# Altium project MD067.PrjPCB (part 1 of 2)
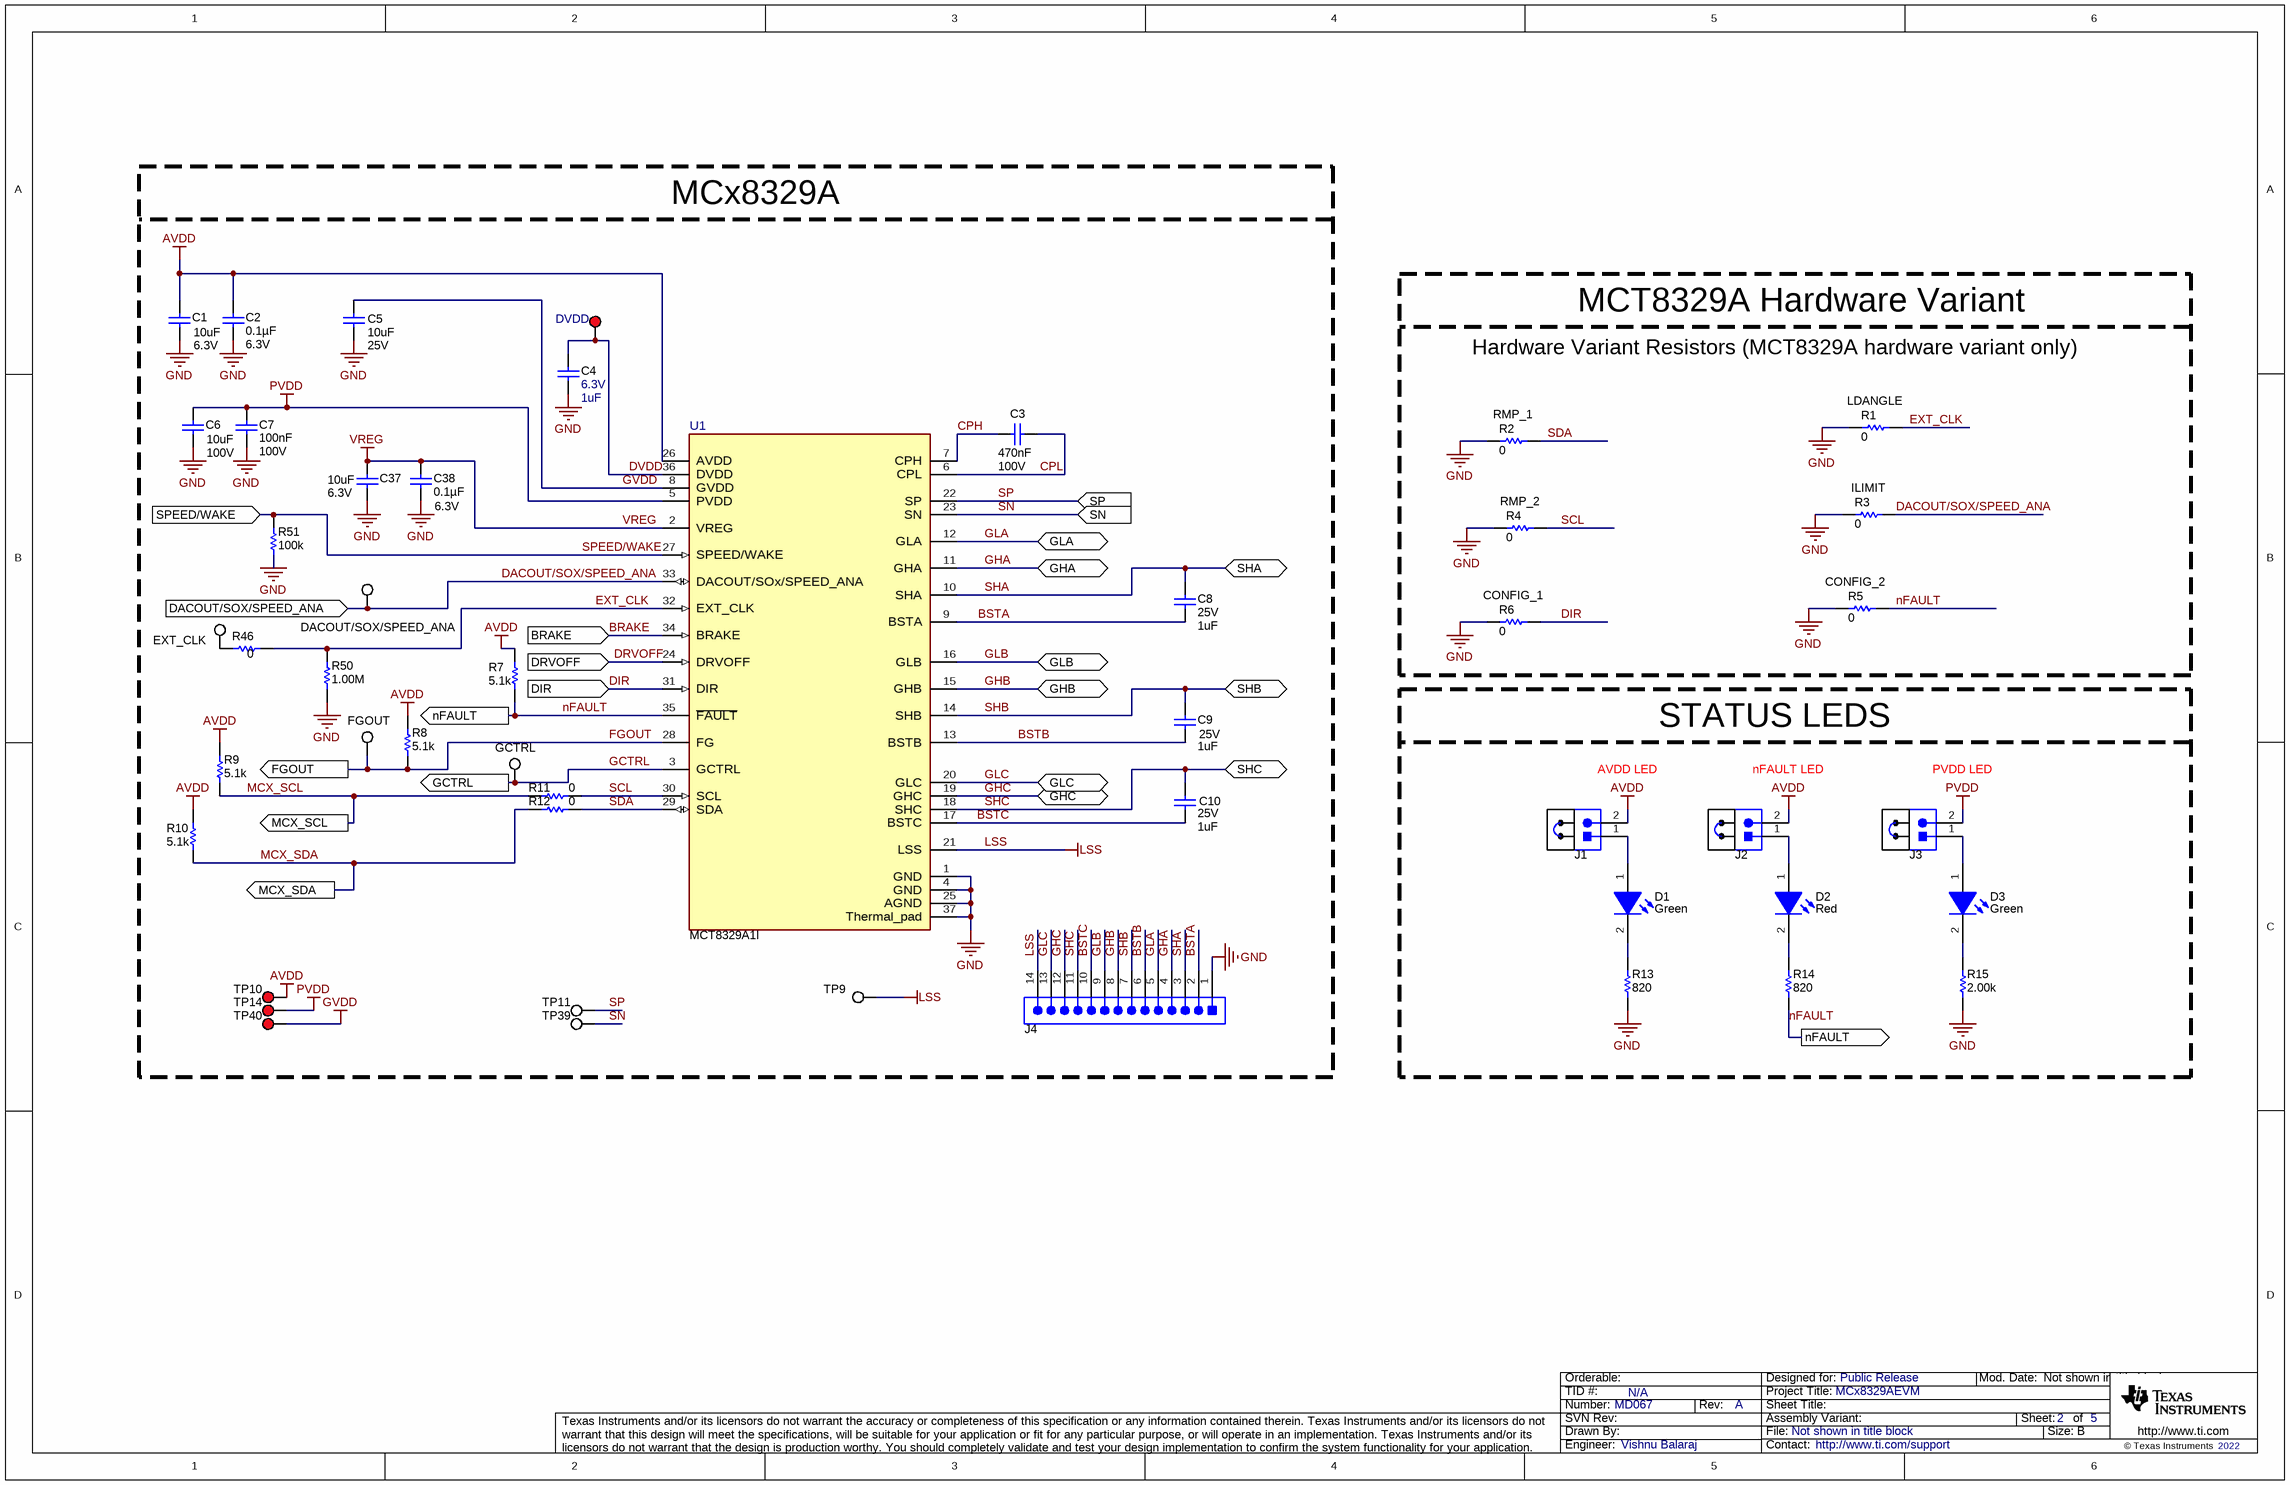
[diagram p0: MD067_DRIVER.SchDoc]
CopyrightYear: 2022; PCB_Layout: Vishnu Balaraj; PCB_Rev: A; PRJ_Customer: Public Release; PRJ_Engineer: Vishnu Balaraj; PRJ_Number: MD067; PRJ_Title: MCx8329AEVM; SCH_Rev: A; TechSupport: http://www.ti.com/support; TID: N/A
5 sheets, 235 parts. Net scope: flat (ports and power ports of the same name join across sheets).
Board file: MD067.PcbDoc
Sheets:
  MD067_DRIVER.SchDoc
  MD067_FETS_AND_POWER_STAGE.SchDoc
  MD067_HARDWARE.SchDoc
  MD067_POWER_AND_CONNECTORS.SchDoc
  MD067_INTERFACE.SchDoc

## Sheet MD067_DRIVER.SchDoc
size 431 x 279 mm; Date: Not shown in title block; ApprovedBy: Not shown in title block; CheckedBy: Not shown in title block; Author: Not shown in title block; CompanyName: Not shown in title block; Engineer: Not shown in title block; Organization: Not shown in title block; Address1: Not shown in title block; Address2: Not shown in title block; Address3: Not shown in title block; Address4: Not shown in title block; DocumentNumber: 2; Revision: Use project parameter SCH_Rev; SheetNumber: 2; SheetTotal: 5; PageSetup: Record=PageOptions¦CenterHorizontal=True¦CenterVertical=True¦PrintScale=1.00¦XCorrection=1.00¦YCorrection=1.00¦PrintKind=0¦BorderSize=5000000¦LeftOffset=0¦BottomOffset=0¦Orientation=2¦PaperLength=1000¦PaperWidth=1000¦Scale=100¦PaperSource=15¦PrintQuality=600¦MediaType=1¦DitherType=10¦PaperKind=Letter¦PrintScaleMode=1

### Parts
C1  VDC_V: 6.3V  ValueDisplayed: 10uF  [0603]  (hidden comment: C0603C106M9PACTU)
C2  ValueDisplayed: 0.1µF  VDC_V: 6.3V  [0603]  (hidden comment: C0603C104K9PAC7867)
C3  Cap_F: 470nF  VDC_V: 100V  [0805_HV]  (hidden comment: GRM21BR72A474KA73L)
C4  VDC_V: 6.3V  ValueDisplayed: 1uF  [0603]  (hidden comment: GRM188R60J105KA01D)
C5  VDC_V: 25V  ValueDisplayed: 10uF  [0603L]  (hidden comment: C1608X5R1E106M080AC)
C6  VDC_V: 100V  ValueDisplayed: 10uF  [2220_280L]  (hidden comment: 22201C106MAT2A)
C7  Cap_F: 100nF  VDC_V: 100V  [0603L]  (hidden comment: GRM188R72A104KA35J)
C8  VDC_V: 25V  ValueDisplayed: 1uF  [0603L]  (hidden comment: C1608X5R1E105K080AC)
C9  VDC_V: 25V  ValueDisplayed: 1uF  [0603L]  (hidden comment: C1608X5R1E105K080AC)
C10  VDC_V: 25V  ValueDisplayed: 1uF  [0603L]  (hidden comment: C1608X5R1E105K080AC)
C37  VDC_V: 6.3V  ValueDisplayed: 10uF  [0603]  (hidden comment: C0603C106M9PACTU)
C38  ValueDisplayed: 0.1µF  VDC_V: 6.3V  [0603]  (hidden comment: C0603C104K9PAC7867)
D1  value Green  [LTST-C170KGKT_Green]  (hidden comment: AVDD)
D2  value Red  [LED_LTST-C170_Red]  (hidden comment: nFAULT)
D3  value Green  [LTST-C170KGKT_Green]  (hidden comment: PVDD)
J1  TSW-102-07-G-S  [TSW-102-07-G-S]  (value not drawn)
J2  TSW-102-07-G-S  [TSW-102-07-G-S]  (value not drawn)
J3  TSW-102-07-G-S  [TSW-102-07-G-S]  (value not drawn)
J4  TSW-114-07-G-S  [TSW-114-07-G-S]  (value not drawn)
R1  ValueDisplayed: 0  [0603L]  (hidden comment: ERJ-3GEY0R00V)
R2  ValueDisplayed: 0  [0603L]  (hidden comment: ERJ-3GEY0R00V)
R3  ValueDisplayed: 0  [0603L]  (hidden comment: ERJ-3GEY0R00V)
R4  ValueDisplayed: 0  [0603L]  (hidden comment: ERJ-3GEY0R00V)
R5  ValueDisplayed: 0  [0603L]  (hidden comment: ERJ-3GEY0R00V)
R6  ValueDisplayed: 0  [0603L]  (hidden comment: ERJ-3GEY0R00V)
R7  ValueDisplayed: 5.1k  [0603L]  (hidden comment: CRCW06035K10JNEA)
R8  ValueDisplayed: 5.1k  [0603L]  (hidden comment: CRCW06035K10JNEA)
R9  ValueDisplayed: 5.1k  [0603L]  (hidden comment: CRCW06035K10JNEA)
R10  ValueDisplayed: 5.1k  [0603L]  (hidden comment: CRCW06035K10JNEA)
R11  ValueDisplayed: 0  [0603L]  (hidden comment: ERJ-3GEY0R00V)
R12  ValueDisplayed: 0  [0603L]  (hidden comment: ERJ-3GEY0R00V)
R13  ValueDisplayed: 820  [0603L]  (hidden comment: RC0603JR-07820RL)
R14  ValueDisplayed: 820  [0603L]  (hidden comment: RC0603JR-07820RL)
R15  ValueDisplayed: 2.00k  [0603L]  (hidden comment: RG1608P-202-B-T5)
R46  Res_ohm: 0  [0603]  (hidden comment: ERJ-3GEY0R00V)
R50  ValueDisplayed: 1.00M  [0603]  (hidden comment: RMCF0603FG1M00)
R51  ValueDisplayed: 100k  [0603]  (hidden comment: RT0603BRD07100KL)
SH-J1  SNT-100-BK-G  [SNT-100-BK-G]  (value not drawn)
SH-J2  SNT-100-BK-G  [SNT-100-BK-G]  (value not drawn)
SH-J3  SNT-100-BK-G  [SNT-100-BK-G]  (value not drawn)
TP1  DVDD  [Keystone5000]
TP2  DACOUT/SOX/SPEED_ANA  [Keystone5002]
TP3  EXT_CLK  [Keystone5002]
TP4  FGOUT  [Keystone5002]
TP5  GCTRL  [Keystone5002]
TP9  LSS  [Testpoint_Keystone_Miniature]  (value not drawn)
TP10  AVDD  [Keystone5000]  (value not drawn)
TP11  SP  [Testpoint_Keystone_Miniature]  (value not drawn)
TP14  PVDD  [Keystone5000]  (value not drawn)
TP39  SN  [Testpoint_Keystone_Miniature]  (value not drawn)
TP40  GVDD  [Keystone5000]  (value not drawn)
U1  MCT8329A1I  [REE0036A-MFG]

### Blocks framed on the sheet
MCx8329A: C1-C10 C37 C38 J4 R7-R12 R46 R50 R51 TP1-TP5 TP9-TP11 TP14 TP39 TP40 U1
MCT8329A Hardware Variant: R1-R6
STATUS LEDS: D1-D3 J1-J3 R13-R15 SH-J1-SH-J3

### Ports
BRAKE (in), DACOUT/SOX/SPEED_ANA (in), DIR (in), DRVOFF (in), FGOUT (out), GCTRL (out), GHA (bidir), GHB (bidir), GHC (bidir), GLA (bidir), GLB (bidir), GLC (bidir), MCX_SCL (out), MCX_SDA (out), nFAULT (out), SHA (bidir), SHB (bidir), SHC (bidir), SN (in), SP (in), SPEED/WAKE (in)

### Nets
AVDD: C1.1 C2.1 J1.2 J2.2 R7.1 R8.2 R9.2 R10.2 TP10.1 U1.26(AVDD)
GND: C1.2 C2.2 C4.2 C5.2 C6.2 C7.2 C37.2 C38.2 J4.1 R1.2 R2.2 R3.2 R4.2 R5.2 R6.2 R13.1 R15.1 R50.1 R51.1 U1.1(GND) U1.4(GND) U1.25(AGND) U1.37(Thermal_pad)
GVDD: C5.1 TP40.1 U1.8(GVDD)
LSS: J4.14 TP9.1 U1.21(LSS)
PVDD: C6.1 C7.1 J3.2 TP14.1 U1.5(PVDD)
VREG: C37.1 C38.1 U1.2(VREG)
BRAKE: U1.34(BRAKE) ; port BRAKE
BSTA: C8.2 J4.2 U1.9(BSTA)
BSTB: C9.1 J4.6 U1.13(BSTB)
BSTC: C10.1 J4.10 U1.17(BSTC)
CPH: C3.1 U1.7(CPH)
CPL: C3.2 U1.6(CPL)
DACOUT/SOX/SPEED_ANA: R3.1 TP2.1 U1.33(DACOUT/SOx/SPEED_ANA) ; port DACOUT/SOX/SPEED_ANA
DIR: R6.1 U1.31(DIR) ; port DIR
DRVOFF: U1.24(DRVOFF) ; port DRVOFF
DVDD: C4.1 TP1.1 U1.36(DVDD)
EXT_CLK: R1.1 R46.2 R50.2 U1.32(EXT_CLK)
FGOUT: R8.1 TP4.1 U1.28(FG) ; port FGOUT
GCTRL: TP5.1 U1.3(GCTRL) ; port GCTRL
GHA: J4.4 U1.11(GHA) ; port GHA
GHB: J4.8 U1.15(GHB) ; port GHB
GHC: J4.12 U1.19(GHC) ; port GHC
GLA: J4.5 U1.12(GLA) ; port GLA
GLB: J4.9 U1.16(GLB) ; port GLB
GLC: J4.13 U1.20(GLC) ; port GLC
MCX_SCL: R9.1 R11.1 ; port MCX_SCL
MCX_SDA: R10.1 R12.1 ; port MCX_SDA
nFAULT: R5.1 R7.2 R14.1 U1.35(~{FAULT}) ; port nFAULT
SCL: R4.1 R11.2 U1.30(SCL)
SDA: R2.1 R12.2 U1.29(SDA)
SHA: C8.1 J4.3 U1.10(SHA) ; port SHA
SHB: C9.2 J4.7 U1.14(SHB) ; port SHB
SHC: C10.2 J4.11 U1.18(SHC) ; port SHC
SN: TP39.1 U1.23(SN) ; port SN
SP: TP11.1 U1.22(SP) ; port SP
SPEED/WAKE: R51.2 U1.27(SPEED/WAKE) ; port SPEED/WAKE
NetD1_1: D1.1(A) J1.1
NetD1_2: D1.2(K) R13.2
NetD2_1: D2.1(A) J2.1
NetD2_2: D2.2(K) R14.2
NetD3_1: D3.1(A) J3.1
NetD3_2: D3.2(K) R15.2
NetR46_1: R46.1 TP3.1

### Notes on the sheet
- Hardware Variant Resistors (MCT8329A hardware variant only)
- (near R2) RMP_1
- (near R1) LDANGLE
- (near R4) RMP_2
- (near R3) ILIMIT
- (near R6) CONFIG_1
- (near R5) CONFIG_2
- AVDD LED
- nFAULT LED
- PVDD LED

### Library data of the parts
C1 C37 = CMP-0006872-5: CAP, CERM, 10 uF, 6.3 V, +/- 20%, X5R, 0603; Manufacturer: Kemet; TaMin_C: -55°C; ESR_ohm: 4m; Polarized: N; SizeAreaWB_mm2: 4.68; Value1: 0.004 ohm; U/M: EA; Value: 10uF; TaMax_C: 85°C; SizeZ_mm: 1; SizeX_mm: 1.6; SizeY_mm: 0.8; SizeArea_mm2: 1.28; Cap_F: 10µF; IRMS_A: 8.9A; AEC Category: Q200
C2 C38 = CMP-0085846-1: CAP, CERM, 0.1 µF, 6.3 V,+/- 10%, X5R, 0603; Manufacturer: Kemet; SizeAreaWB_mm2: 4.68; SizeArea_mm2: 1.28; SizeZ_mm: 1; Polarized: N; Cap_F: 100nF; TaMin_C: -55°C; AEC Category: Q200; SizeX_mm: 1.6; Value: 0.1uF; U/M: EA; SizeY_mm: 0.8; TaMax_C: 85°C
C3 = CMP-0008374-1: CAP, CERM, 0.47 uF, 100 V, +/- 10%, X7R, 0805; Manufacturer: MuRata; TaMin_C: -55°C; Polarized: N; SizeAreaWB_mm2: 6.75; Value1: Unknown; U/M: EA; Value: 0.47uF; TaMax_C: 125°C; SizeZ_mm: 1.45; SizeX_mm: 2; SizeY_mm: 1.25; Cap_Case: 0805; SizeArea_mm2: 2.5; AEC Category: Q200
C4 = CMP-0007302-2: CAP, CERM, 1 uF, 6.3 V, +/- 10%, X5R, 0603; Manufacturer: MuRata; TaMin_C: -55°C; Polarized: N; SizeAreaWB_mm2: 4.68; Value1: Unknown; U/M: EA; Value: 1uF; TaMax_C: 85°C; SizeZ_mm: 1; SizeX_mm: 1.6; SizeY_mm: 0.8; SizeArea_mm2: 1.28; Cap_F: 1µF; AEC Category: Q200
C5 = CMP-0007007-5: CAP, CERM, 10 uF, 25 V, +/- 20%, X5R, 0603; Manufacturer: TDK; TaMin_C: -55°C; ESR_ohm: 4.639m; Polarized: N; SizeAreaWB_mm2: 4.68; Value1: 0.004639 ohm; U/M: EA; Value: 10uF; TaMax_C: 85°C; SizeZ_mm: 1; SizeX_mm: 1.6; SizeY_mm: 0.8; Cap_Case: 0603; SizeArea_mm2: 1.28; Cap_F: 10µF; IRMS_A: 2.41407A; AEC Category: Q200
C6 = CMP-0009304-2: CAP, CERM, 10 uF, 100 V, +/- 20%, X7R, 2220; Manufacturer: AVX; TaMin_C: -55°C; Polarized: N; SizeAreaWB_mm2: 53.9; Value1: Unknown; U/M: EA; Value: 10uF; TaMax_C: 125°C; SizeZ_mm: 2.8; SizeX_mm: 5.7; SizeY_mm: 5; Cap_Case: 2220; SizeArea_mm2: 28.5; Cap_F: 10µF; AEC Category: Q200
C7 = CMP-0007470-5: CAP, CERM, 0.1 uF, 100 V, +/- 10%, X7R, 0603; Manufacturer: MuRata; TaMin_C: -55°C; Polarized: N; SizeAreaWB_mm2: 4.68; Value1: Unknown; U/M: EA; Value: 0.1uF; TaMax_C: 125°C; SizeZ_mm: 1; SizeX_mm: 1.6; SizeY_mm: 0.8; Cap_Case: 0603; SizeArea_mm2: 1.28; AEC Category: Q200
C8-C10 = CMP-0007006-5: CAP, CERM, 1 uF, 25 V, +/- 10%, X5R, 0603; Manufacturer: TDK; TaMin_C: -55°C; Polarized: N; SizeAreaWB_mm2: 4.68; Value1: Unknown; U/M: EA; Value: 1uF; TaMax_C: 85°C; SizeZ_mm: 1; SizeX_mm: 1.6; SizeY_mm: 0.8; Cap_Case: 0603; SizeArea_mm2: 1.28; Cap_F: 1µF; AEC Category: Q200
D1 D3 = CMP-0002888-2: LED, Green, SMD; Manufacturer: Lite-On; PartNumber: LTST-C170KGKT; Io_A: 20mA; Value1: W; Vf_V: 2V; Type: AlInGaP
D2 = CMP-0002829-3: LED, Red, SMD; Manufacturer: Lite-On; PartNumber: LTST-C170KRKT; Io_A: 20mA; SizeAreaWB_mm2: 6.75; Value1: W; SizeZ_mm: 1.2; SizeX_mm: 2; SizeY_mm: 1.25; Vf_V: 2V; SizeArea_mm2: 2.5; Type: AlInGaP
J1-J3 = CMP-0075405-3: Header, 100mil, 2x1, Gold, TH; Manufacturer: Samtec; Current_A: 6.3A; Green_Lifecycle: Active; Pitch_mm: 2.54; Cert_CSA: Y; Cert_VDE: N; Green_REACh: Passed; Row_Count: 1; Gender: Male; Voltage_V: 550V
J4 = CMP-0075428-1: Header, 100mil, 14x1, Gold, TH; Manufacturer: Samtec; Pitch_mm: 2.54; Cert_VDE: N; Gender: Male; Cert_CSA: Y; Voltage_V: 550V; Green_REACh: Passed; Current_A: 6.3A; CT: False; Green_Lifecycle: Active; Row_Count: 1; CNHeader: True
R1-R6 R11 R12 R46 = CMP-0025874-4: RES, 0, 5%, 0.1 W, AEC-Q200 Grade 0, 0603; Manufacturer: Panasonic; Power_W: 100mW; TempCo: 600 ppm/C; Value_Code: 0000; Value: 0; EIA_Code: E24; SizeX_mm: 1.6; SizeY_mm: 0.8; SizeZ_mm: 1; Value2: 0.1W; SizeArea_mm2: 1.28; AEC Qualified: Y; VDC_V: 50V; AEC Category: Q200; SizeAreaWB_mm2: 4.68
R7-R10 = CMP-0025830-4: RES, 5.1 k, 5%, 0.1 W, AEC-Q200 Grade 0, 0603; Manufacturer: Vishay-Dale; Power_W: 100mW; TempCo: 200 ppm/C; Value_Code: 5k10; Value: 5.1k; EIA_Code: E24; SizeX_mm: 1.6; SizeY_mm: 0.8; SizeZ_mm: 1; Value2: 0.1W; SizeArea_mm2: 1.28; AEC Qualified: Y; VDC_V: 75V; AEC Category: Q200; AEC Grade: 0
R13 R14 = CMP-0025941-5: RES, 820, 5%, 0.1 W, 0603; Manufacturer: Yageo; Power_W: 100mW; TempCo: 100 ppm/C; Value_Code: 820R; Value: 820; EIA_Code: E24; SizeX_mm: 1.6; SizeY_mm: 0.8; SizeZ_mm: 1; Value2: 0.1W; SizeArea_mm2: 1.28; AEC Qualified: N; VDC_V: 75V; AEC Category: Q200; SizeAreaWB_mm2: 4.68
R15 = CMP-0023463-3: RES, 2.00 k, 0.1%, 0.1 W, 0603; Manufacturer: Susumu Co Ltd; Power_W: 100mW; TempCo: 25 ppm/C; Value_Code: 2k00; U/M: EA; Value: 2.00k; EIA_Code: E192; Res_ohm: 2k; SizeX_mm: 1.6; SizeY_mm: 0.8; SizeZ_mm: 1; Value2: 0.1W; SizeArea_mm2: 1.28; VDC_V: 75V; AEC Category: Q200
R50 = CMP-0085900-1: RES, 1.00 M, 1%, 0.1 W, AEC-Q200 Grade 0, 0603; Manufacturer: Stackpole Electronics Inc; AEC Category: Q200; Res_ohm: 1M; SizeX_mm: 1.6; SizeY_mm: 0.8; Value: 1.00Meg; SizeAreaWB_mm2: 4.68; SizeArea_mm2: 1.28; Power_W: 100mW; AEC Qualified: Y; EIA_Code: E96; AEC Grade: 0; Value_Code: 1M00; Value2: 0.1W; TempCo: 100 ppm/C; SizeZ_mm: 1
R51 = CMP-0023630-1: RES, 100 k, 0.1%, 0.1 W, 0603; Manufacturer: Yageo America; Power_W: 100mW; TempCo: 25 ppm/C; U/M: EA; Value: 100k; EIA_Code: E192; SizeX_mm: 1.6; SizeY_mm: 0.8; SizeZ_mm: 1; Value2: 0.1W; SizeArea_mm2: 1.28; VDC_V: 75V; AEC Category: Q200
SH-J1-SH-J3 = CMP-0003623-3: Shunt, 100mil, Gold plated, Black; Alternate PartNumber: 969102-0000-DA; Manufacturer: Samtec; Alternate Manufacturer: 3M; Value: 1x2
TP1 TP10 TP14 TP40 = CMP-0055137-1: Test Point, Miniature, Red, TH; PartNumber: 5000; Manufacturer: Keystone; ContactFinish: Silver; CNHeader: FALSE; CT: TRUE; Green_Lifecycle: Active; Green_REACh: Passed
TP2-TP5 = CMP-0055139-1: Test Point, Miniature, White, TH; Manufacturer: Keystone; CNHeader: FALSE; Green_Lifecycle: Active; Green_REACh: Passed; ContactFinish: Silver; CT: TRUE
TP9 TP11 TP39 = CMP-0055152-1: Test Point, Miniature, SMT; Manufacturer: Keystone; CNHeader: FALSE; Green_Lifecycle: Active; Green_REACh: Passed; CT: TRUE
U1 = CMP-0095893-1: High Speed Sensorless Trapezoidal Control 4.5 to 60 V Three-phase BLDC Gate Driver; Manufacturer: Texas Instruments; Number Of Outputs: 3; AEC Qualified: No; Standoff Height: 0mm; Min Supply Voltage: 4.5V; Motor Type: Brushless DC; SizeZ_mm: 0.8mm; TaMin_C: -40°C; Switching Frequency: 100kHz; TJmax_C: +150°C; Max Supply Voltage: 60V; TaMax_C: +125°C

## Sheet MD067_FETS_AND_POWER_STAGE.SchDoc
size 431 x 279 mm; Date: Not shown in title block; ApprovedBy: Not shown in title block; CheckedBy: Not shown in title block; Author: Not shown in title block; CompanyName: Not shown in title block; Engineer: Not shown in title block; Organization: Not shown in title block; Address1: Not shown in title block; Address2: Not shown in title block; Address3: Not shown in title block; Address4: Not shown in title block; DocumentNumber: 3; Revision: Use project parameter SCH_Rev; SheetNumber: 3; SheetTotal: 5; PageSetup: Record=PageOptions¦CenterHorizontal=True¦CenterVertical=True¦PrintScale=1.00¦XCorrection=1.00¦YCorrection=1.00¦PrintKind=0¦BorderSize=5000000¦LeftOffset=0¦BottomOffset=0¦Orientation=2¦PaperLength=1000¦PaperWidth=1000¦Scale=100¦PaperSource=15¦PrintQuality=600¦MediaType=1¦DitherType=10¦PaperKind=Letter¦PrintScaleMode=1
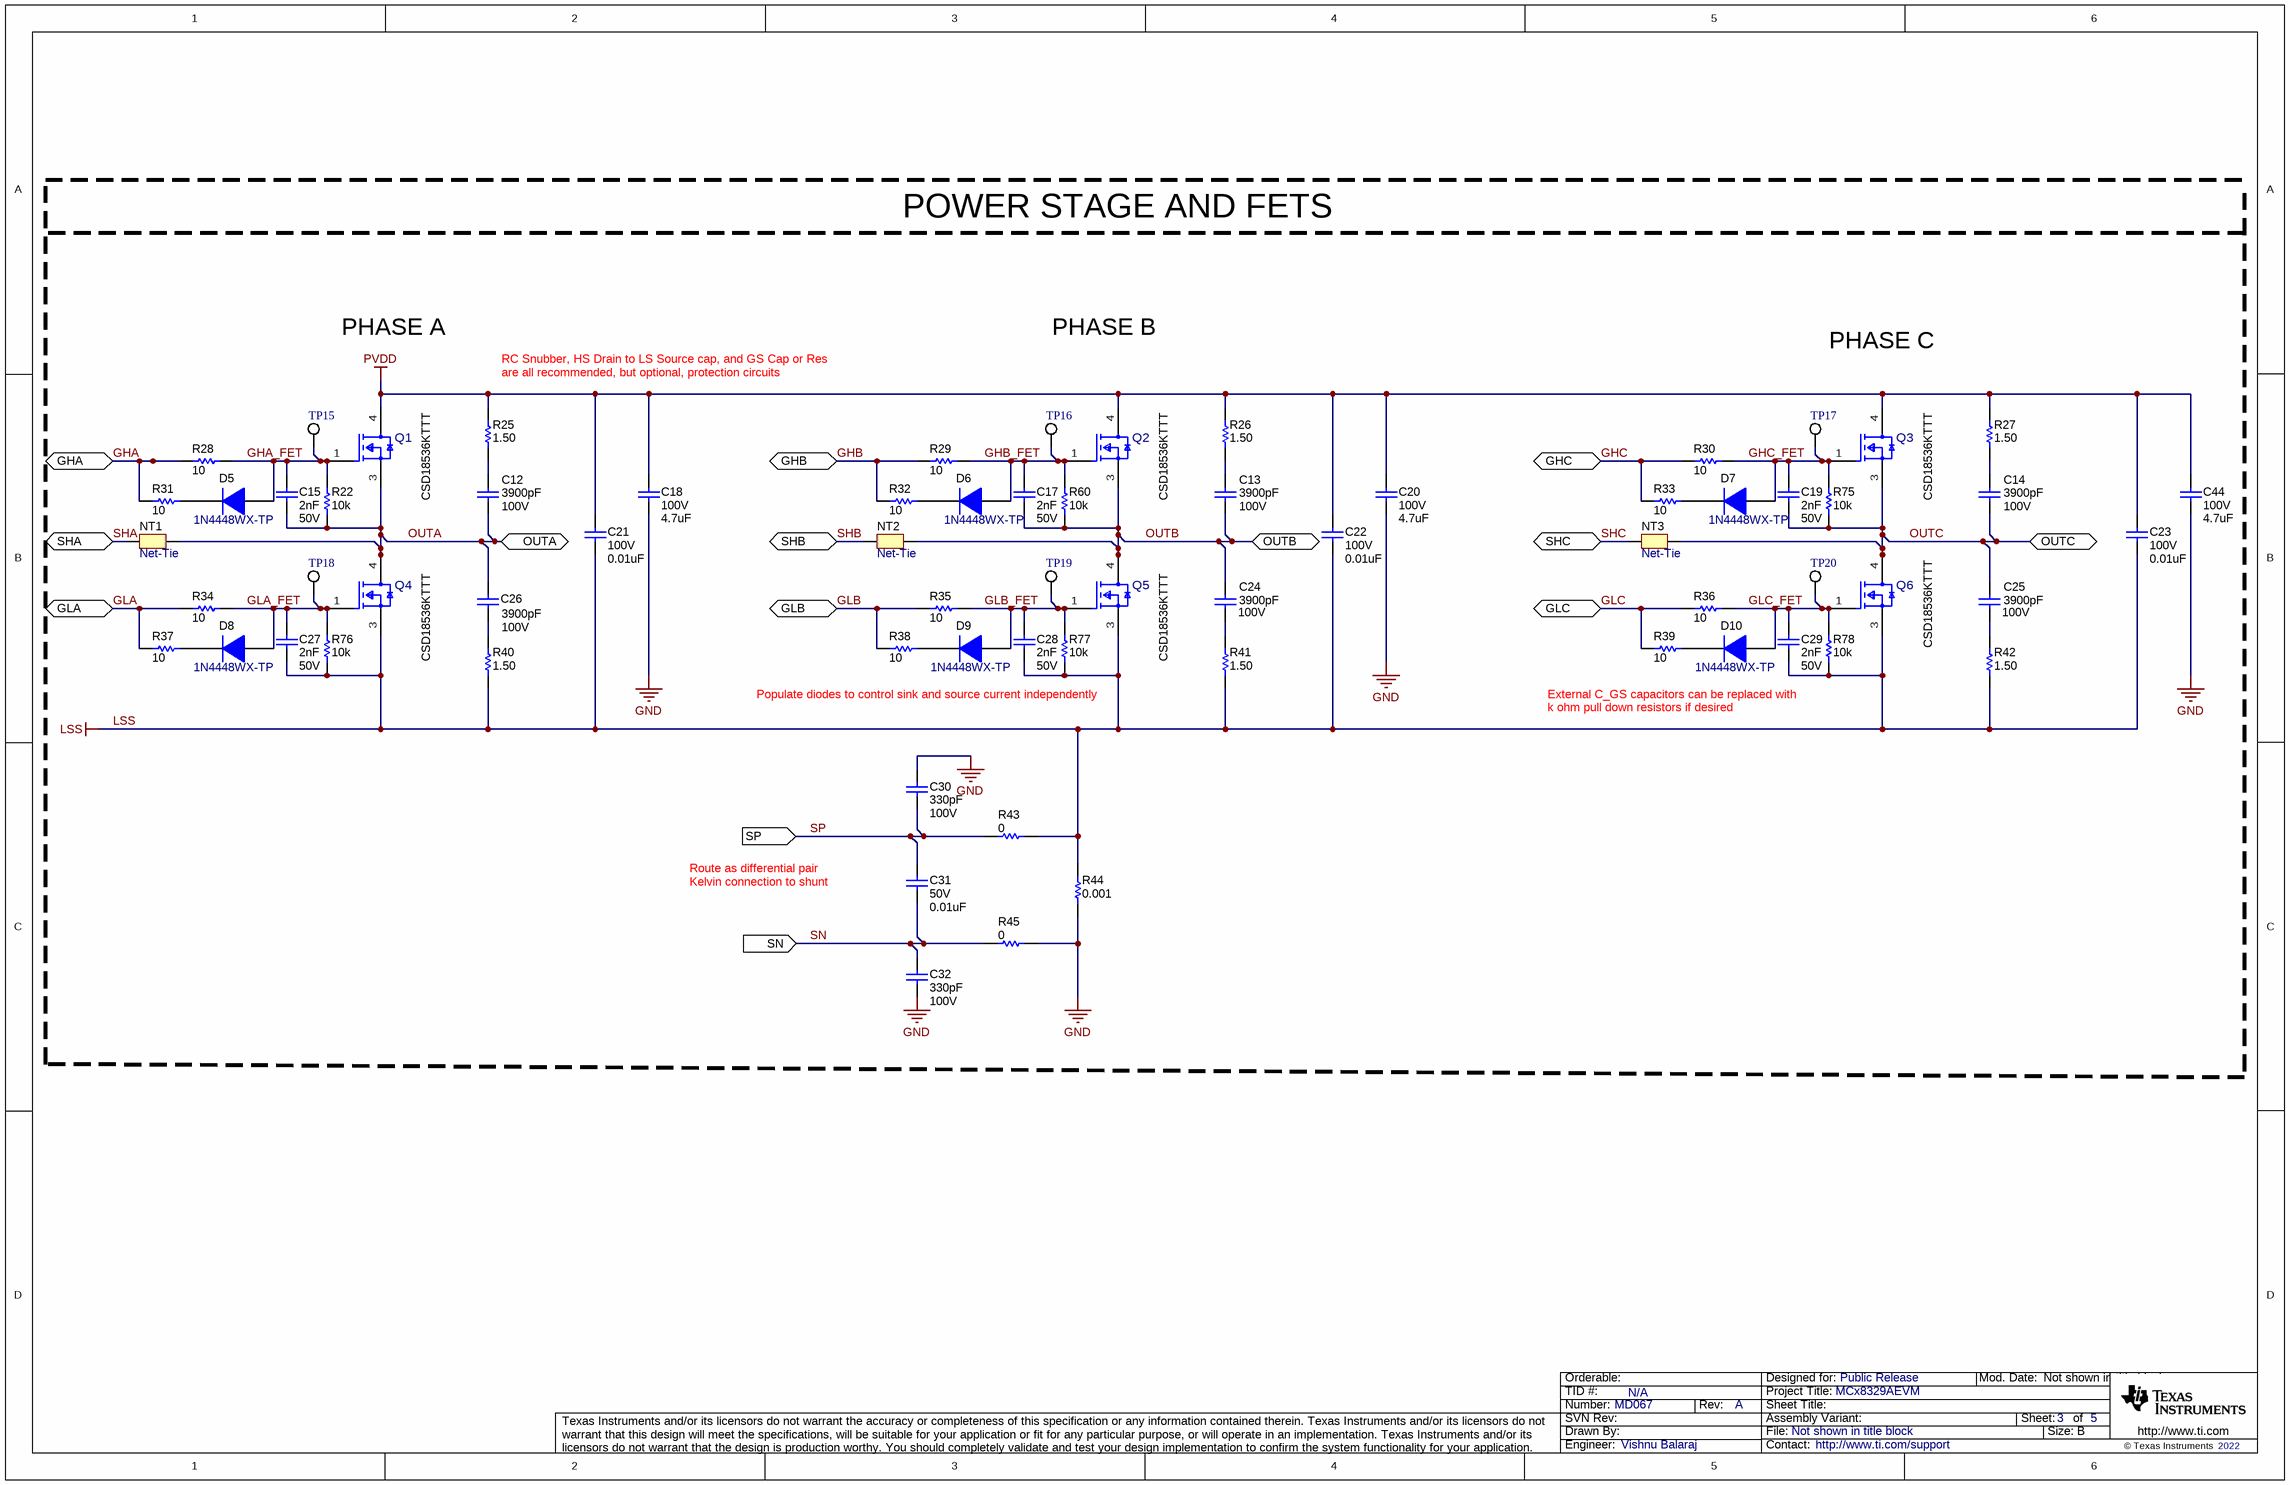
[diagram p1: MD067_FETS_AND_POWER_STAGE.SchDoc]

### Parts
C12  VDC_V: 100V  ValueDisplayed: 3900pF  [1206L]  (hidden comment: 12061C392KAZ2A)
C13  VDC_V: 100V  ValueDisplayed: 3900pF  [1206L]  (hidden comment: 12061C392KAZ2A)
C14  VDC_V: 100V  ValueDisplayed: 3900pF  [1206L]  (hidden comment: 12061C392KAZ2A)
C15  Cap_F: 2nF  VDC_V: 50V  [0603L]  (hidden comment: GRM188R71H202KA01D)  (no BOM)
C17  Cap_F: 2nF  VDC_V: 50V  [0603L]  (hidden comment: GRM188R71H202KA01D)  (no BOM)
C18  VDC_V: 100V  ValueDisplayed: 4.7uF  [1210_220L]  (hidden comment: GRM32DC72A475KE01L)
C19  Cap_F: 2nF  VDC_V: 50V  [0603L]  (hidden comment: GRM188R71H202KA01D)  (no BOM)
C20  VDC_V: 100V  ValueDisplayed: 4.7uF  [1210_220L]  (hidden comment: GRM32DC72A475KE01L)
C21  VDC_V: 100V  ValueDisplayed: 0.01uF  [0805L]  (hidden comment: 08051C103JAT2A)
C22  VDC_V: 100V  ValueDisplayed: 0.01uF  [0805L]  (hidden comment: 08051C103JAT2A)
C23  VDC_V: 100V  ValueDisplayed: 0.01uF  [0805L]  (hidden comment: 08051C103JAT2A)
C24  VDC_V: 100V  ValueDisplayed: 3900pF  [1206L]  (hidden comment: 12061C392KAZ2A)
C25  VDC_V: 100V  ValueDisplayed: 3900pF  [1206L]  (hidden comment: 12061C392KAZ2A)
C26  VDC_V: 100V  ValueDisplayed: 3900pF  [1206L]  (hidden comment: 12061C392KAZ2A)
C27  Cap_F: 2nF  VDC_V: 50V  [0603L]  (hidden comment: GRM188R71H202KA01D)  (no BOM)
C28  Cap_F: 2nF  VDC_V: 50V  [0603L]  (hidden comment: GRM188R71H202KA01D)  (no BOM)
C29  Cap_F: 2nF  VDC_V: 50V  [0603L]  (hidden comment: GRM188R71H202KA01D)  (no BOM)
C30  Cap_F: 330pF  VDC_V: 100V  [0603L]  (hidden comment: 06031C331KAT2A)
C31  VDC_V: 50V  ValueDisplayed: 0.01uF  [0603L]  (hidden comment: C1608NP01H103J080AA)
C32  Cap_F: 330pF  VDC_V: 100V  [0603L]  (hidden comment: 06031C331KAT2A)
C44  VDC_V: 100V  ValueDisplayed: 4.7uF  [1210_220L]  (hidden comment: GRM32DC72A475KE01L)
D5  1N4448WX-TP  [SOD-323]
D6  1N4448WX-TP  [SOD-323]
D7  1N4448WX-TP  [SOD-323]
D8  1N4448WX-TP  [SOD-323]
D9  1N4448WX-TP  [SOD-323]
D10  1N4448WX-TP  [SOD-323]
NT1  Net-Tie  [Net-Tie_0805_HV_NoOverlay]  (net tie, no BOM)
NT2  Net-Tie  [Net-Tie_0805_HV_NoOverlay]  (net tie, no BOM)
NT3  Net-Tie  [Net-Tie_0805_HV_NoOverlay]  (net tie, no BOM)
Q1  CSD18536KTTT  [KTT0002A-MFG]
Q2  CSD18536KTTT  [KTT0002A-MFG]
Q3  CSD18536KTTT  [KTT0002A-MFG]
Q4  CSD18536KTTT  [KTT0002A-MFG]
Q5  CSD18536KTTT  [KTT0002A-MFG]
Q6  CSD18536KTTT  [KTT0002A-MFG]
R22  ValueDisplayed: 10k  [0603L]  (hidden comment: CRCW060310K0JNEA)
R25  ValueDisplayed: 1.50  [1206L]  (hidden comment: CRCW12061R50FKEA)
R26  ValueDisplayed: 1.50  [1206L]  (hidden comment: CRCW12061R50FKEA)
R27  ValueDisplayed: 1.50  [1206L]  (hidden comment: CRCW12061R50FKEA)
R28  ValueDisplayed: 10  [0603L]  (hidden comment: CRCW060310R0JNEA)
R29  ValueDisplayed: 10  [0603L]  (hidden comment: CRCW060310R0JNEA)
R30  ValueDisplayed: 10  [0603L]  (hidden comment: CRCW060310R0JNEA)
R31  ValueDisplayed: 10  [0603L]  (hidden comment: CRCW060310R0JNEA)
R32  ValueDisplayed: 10  [0603L]  (hidden comment: CRCW060310R0JNEA)
R33  ValueDisplayed: 10  [0603L]  (hidden comment: CRCW060310R0JNEA)
R34  ValueDisplayed: 10  [0603L]  (hidden comment: CRCW060310R0JNEA)
R35  ValueDisplayed: 10  [0603L]  (hidden comment: CRCW060310R0JNEA)
R36  ValueDisplayed: 10  [0603L]  (hidden comment: CRCW060310R0JNEA)
R37  ValueDisplayed: 10  [0603L]  (hidden comment: CRCW060310R0JNEA)
R38  ValueDisplayed: 10  [0603L]  (hidden comment: CRCW060310R0JNEA)
R39  ValueDisplayed: 10  [0603L]  (hidden comment: CRCW060310R0JNEA)
R40  ValueDisplayed: 1.50  [1206L]  (hidden comment: CRCW12061R50FKEA)
R41  ValueDisplayed: 1.50  [1206L]  (hidden comment: CRCW12061R50FKEA)
R42  ValueDisplayed: 1.50  [1206L]  (hidden comment: CRCW12061R50FKEA)
R43  ValueDisplayed: 0  [0603L]  (hidden comment: ERJ-3GEY0R00V)
R44  ValueDisplayed: 0.001  [CSS2725_001]  (hidden comment: CSS2725FT1L00)
R45  ValueDisplayed: 0  [0603L]  (hidden comment: ERJ-3GEY0R00V)
R60  ValueDisplayed: 10k  [0603L]  (hidden comment: CRCW060310K0JNEA)
R75  ValueDisplayed: 10k  [0603L]  (hidden comment: CRCW060310K0JNEA)
R76  ValueDisplayed: 10k  [0603L]  (hidden comment: CRCW060310K0JNEA)
R77  ValueDisplayed: 10k  [0603L]  (hidden comment: CRCW060310K0JNEA)
R78  ValueDisplayed: 10k  [0603L]  (hidden comment: CRCW060310K0JNEA)
TP15  GHA_FET  [Testpoint_Keystone_Miniature]  (value not drawn)
TP16  GHB_FET  [Testpoint_Keystone_Miniature]  (value not drawn)
TP17  GHC_FET  [Testpoint_Keystone_Miniature]  (value not drawn)
TP18  GLA_FET  [Testpoint_Keystone_Miniature]  (value not drawn)
TP19  GLB_FET  [Testpoint_Keystone_Miniature]  (value not drawn)
TP20  GLC_FET  [Testpoint_Keystone_Miniature]  (value not drawn)

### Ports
GHA (bidir), GHB (bidir), GHC (bidir), GLA (bidir), GLB (bidir), GLC (bidir), OUTA (bidir), OUTB (bidir), OUTC (bidir), SHA (bidir), SHB (bidir), SHC (bidir), SN (in), SP (in)

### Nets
GND: C18.2 C20.2 C30.1 C32.2 C44.2 R44.1 R45.2
LSS: C21.2 C22.2 C23.2 C27.2 C28.2 C29.2 Q4.3(Source) Q5.3(Source) Q6.3(Source) R40.1 R41.1 R42.1 R43.2 R44.2 R76.1 R77.1 R78.1
PVDD: C18.1 C20.1 C21.1 C22.1 C23.1 C44.1 Q1.4(Drain) Q2.4(Drain) Q3.4(Drain) R25.1 R26.1 R27.1
GHA: R28.1 R31.1 ; port GHA
GHA_FET: C15.1 D5.2(A) Q1.1(Gate) R22.2 R28.2 TP15.1
GHB: R29.1 R32.1 ; port GHB
GHB_FET: C17.1 D6.2(A) Q2.1(Gate) R29.2 R60.2 TP16.1
GHC: R30.1 R33.1 ; port GHC
GHC_FET: C19.1 D7.2(A) Q3.1(Gate) R30.2 R75.2 TP17.1
GLA: R34.1 R37.1 ; port GLA
GLA_FET: C27.1 D8.2(A) Q4.1(Gate) R34.2 R76.2 TP18.1
GLB: R35.1 R38.1 ; port GLB
GLB_FET: C28.1 D9.2(A) Q5.1(Gate) R35.2 R77.2 TP19.1
GLC: R36.1 R39.1 ; port GLC
GLC_FET: C29.1 D10.2(A) Q6.1(Gate) R36.2 R78.2 TP20.1
OUTA: C12.1 C15.2 C26.1 NT1.2 Q1.3(Source) Q4.4(Drain) R22.1 ; port OUTA
OUTB: C13.1 C17.2 C24.1 NT2.2 Q2.3(Source) Q5.4(Drain) R60.1 ; port OUTB
OUTC: C14.1 C19.2 C25.1 NT3.2 Q3.3(Source) Q6.4(Drain) R75.1 ; port OUTC
SHA: NT1.1 ; port SHA
SHB: NT2.1 ; port SHB
SHC: NT3.1 ; port SHC
SN: C31.2 C32.1 R45.1 ; port SN
SP: C30.2 C31.1 R43.1 ; port SP
NetC12_2: C12.2 R25.2
NetC13_2: C13.2 R26.2
NetC14_2: C14.2 R27.2
NetC24_2: C24.2 R41.2
NetC25_2: C25.2 R42.2
NetC26_2: C26.2 R40.2
NetD5_1: D5.1(K) R31.2
NetD6_1: D6.1(K) R32.2
NetD7_1: D7.1(K) R33.2
NetD8_1: D8.1(K) R37.2
NetD9_1: D9.1(K) R38.2
NetD10_1: D10.1(K) R39.2

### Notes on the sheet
- POWER STAGE AND FETS
- PHASE A
- RC Snubber, HS Drain to LS Source cap, and GS Cap or Res
- PHASE B
- PHASE C
- (near R25) are all recommended, but optional, protection circuits
- Populate diodes to control sink and source current independently
- External C_GS capacitors can be replaced with
- k ohm pull down resistors if desired
- Route as differential pair
- Kelvin connection to shunt

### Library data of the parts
C12-C14 C24-C26 = CMP-0008756-2: CAP CER 3900PF 100V X7R 1206; Manufacturer: AVX Corporation; TaMin_C: -55°C; Polarized: N; SizeAreaWB_mm2: 10.92; Value1: Unknown; U/M: EA; TaMax_C: 125°C; Tolerance_%: 10%; SizeZ_mm: 1.35; SizeX_mm: 3.2; SizeY_mm: 1.6; Cap_Case: 1206; SizeArea_mm2: 5.12; Cap_F: 3.9nF; AEC Category: Q200
C15 C17 C19 C27-C29 = CMP-0007441-5: CAP, CERM, 2000 pF, 50 V, +/- 10%, X7R, 0603; Manufacturer: MuRata; TaMin_C: -55°C; Polarized: N; SizeAreaWB_mm2: 4.68; Value1: Unknown; U/M: EA; Value: 2000pF; TaMax_C: 125°C; SizeZ_mm: 1; SizeX_mm: 1.6; SizeY_mm: 0.8; Cap_Case: 0603; SizeArea_mm2: 1.28; AEC Category: Q200
C18 C20 C44 = CMP-0009182-2: CAP, CERM, 4.7 uF, 100 V, +/- 10%, X7S, 1210; Manufacturer: MuRata; TaMin_C: -55°C; Polarized: N; SizeAreaWB_mm2: 14.7; Value1: Unknown; U/M: EA; Value: 4.7uF; TaMax_C: 125°C; SizeZ_mm: 2.2; SizeX_mm: 3.2; SizeY_mm: 2.5; Cap_Case: 1210; SizeArea_mm2: 8; Cap_F: 4.7µF; AEC Category: Q200
C21-C23 = CMP-0007542-2: CAP, CERM, 0.01 uF, 100 V, +/- 5%, X7R, 0805; Manufacturer: AVX; TaMin_C: -55°C; ESR_ohm: 0.078; Polarized: N; SizeAreaWB_mm2: 6.75; Value1: 0.078 ohm; U/M: EA; Value: 0.01uF; TaMax_C: 125°C; SizeZ_mm: 1.45; SizeX_mm: 2; SizeY_mm: 1.25; Cap_Case: 0805; SizeArea_mm2: 2.5; Cap_F: 10nF; AEC Category: Q200
C30 C32 = CMP-0006740-4: CAP, CERM, 330 pF, 100 V, +/- 10%, X7R, 0603; Manufacturer: AVX; TaMin_C: -55°C; ESR_ohm: 0.472; Polarized: N; SizeAreaWB_mm2: 4.68; Value1: 0.472 ohm; U/M: EA; Value: 330pF; TaMax_C: 125°C; SizeZ_mm: 1; SizeX_mm: 1.6; SizeY_mm: 0.8; Cap_Case: 0603; SizeArea_mm2: 1.28; AEC Category: Q200
C31 = CMP-0006998-4: CAP, CERM, 0.01 uF, 50 V, +/- 5%, C0G/NP0, 0603; Manufacturer: TDK; TaMin_C: -55°C; Polarized: N; SizeAreaWB_mm2: 4.68; Value1: Unknown; U/M: EA; Value: 0.01uF; TaMax_C: 150°C; SizeZ_mm: 1; SizeX_mm: 1.6; SizeY_mm: 0.8; Cap_Case: 0603; SizeArea_mm2: 1.28; Cap_F: 10nF; AEC Category: Q200
D5-D10 = CMP-0076911-2: Diode, Switching, 75 V, 0.25 A, SOD-323; Manufacturer: Micro Commercial Components; SizeArea_mm2: 3.645; TJmax_C: 150°C; Vr_V: 75V; SizeY_mm: 1.35; Value: 75V; SizeAreaWB_mm2: 8.695; Green_Lifecycle: Not Set; SizeX_mm: 2.7; AEC Category: Q101; Io_A: 250mA; Green_REACh: Incomplete; Value1: 0.25A; SizeZ_mm: 1.0
NT1-NT3 = CMP-0078142-2: Single point connection between nets.
Q1-Q6 = CMP-0092295-1: MOSFET 60-V, N channel NexFET power MOSFET, single D2PAK, 1.6 mOhm 3-DDPAK/TO-263 -55 to 175; Manufacturer: Texas Instruments; QgTyp_nC: 108nC @ 10V; Threshold Vgs Min: 1.4V; VdsMax_V: 1V; Standoff Height: 0mm; Rdson45_ohm: 1.3m; Reverse Recovery Time: 86ns; ChMode: False; Turn On Delay Time: 11ns; Typ Forward Diode Voltage: 0.9V; Transconductance: 312S; Threshold Vgs Max: 2.2V; Rthja Max: 62°C/W; Drain To Source Breakdown Voltage: 60V; Reverse Recovery Charge: 323nC; TJmax_C: +175°C; AEC Qualified: No; Power_W: 375W; Turn Off Delay Time: 24ns; Number Of Channels: 1; Vgs_V: 20V; SizeZ_mm: 4.95mm; Pulse Drain Current: 400A; IdsMax_A: 200A; Input Capacitace At Vds: 8790pF @ 30V
R22 R60 R75-R78 = CMP-0025701-2: RES, 10 k, 5%, 0.1 W, 0603; Manufacturer: Vishay-Dale; Power_W: 100mW; TempCo: 200 ppm/C; Value_Code: 10k0; U/M: EA; Value: 10k; EIA_Code: E24; SizeX_mm: 1.6; SizeY_mm: 0.8; SizeZ_mm: 1; Value2: 0.1W; SizeArea_mm2: 1.28; VDC_V: 75V; AEC Category: Q200
R25-R27 R40-R42 = CMP-0016763-3: RES, 1.50, 1%, 0.25 W, AEC-Q200 Grade 0, 1206; Manufacturer: Vishay-Dale; Power_W: 250mW; TempCo: 100 ppm/C; Value_Code: 1R50; Value: 1.50; EIA_Code: E96; Res_ohm: 1.5; SizeX_mm: 3.2; SizeY_mm: 1.6; SizeZ_mm: 1.35; Value2: 0.25W; SizeArea_mm2: 5.12; AEC Qualified: Y; VDC_V: 200V; AEC Category: Q200; AEC Grade: 0
R28-R39 = CMP-0025703-4: RES, 10, 5%, 0.1 W, AEC-Q200 Grade 0, 0603; Manufacturer: Vishay-Dale; Power_W: 100mW; TempCo: 200 ppm/C; Value_Code: 10R0; Value: 10; EIA_Code: E24; SizeX_mm: 1.6; SizeY_mm: 0.8; SizeZ_mm: 1; Value2: 0.1W; SizeArea_mm2: 1.28; AEC Qualified: Y; VDC_V: 75V; AEC Category: Q200; AEC Grade: 0
R43 R45 = CMP-0025874-4: as R1 on sheet MD067_DRIVER
R44 = CMP-0015025-2: RES, 0.001, 1%, 4 W, RES_2725; Manufacturer: Stackpole Electronics Inc; Power_W: 4W; TempCo: 50 ppm/C; Value_Code: 1L000; U/M: EA; Value: 0.001; EIA_Code: E96; Res_ohm: 1m; AEC Category: Q200
TP15-TP20 = CMP-0055152-1: as TP9 on sheet MD067_DRIVER

## Sheet MD067_HARDWARE.SchDoc
size 431 x 279 mm; Date: Not shown in title block; ApprovedBy: Not shown in title block; CheckedBy: Not shown in title block; Author: Not shown in title block; CompanyName: Not shown in title block; Engineer: Not shown in title block; Organization: Not shown in title block; Address1: Not shown in title block; Address2: Not shown in title block; Address3: Not shown in title block; Address4: Not shown in title block; DocumentNumber: 5; Revision: Use project parameter SCH_Rev; SheetNumber: 5; SheetTotal: 5; PageSetup: Record=PageOptions¦CenterHorizontal=True¦CenterVertical=True¦PrintScale=1.00¦XCorrection=1.00¦YCorrection=1.00¦PrintKind=0¦BorderSize=5000000¦LeftOffset=0¦BottomOffset=0¦Orientation=2¦PaperLength=1000¦PaperWidth=1000¦Scale=100¦PaperSource=15¦PrintQuality=600¦MediaType=1¦DitherType=10¦PaperKind=Letter¦PrintScaleMode=1
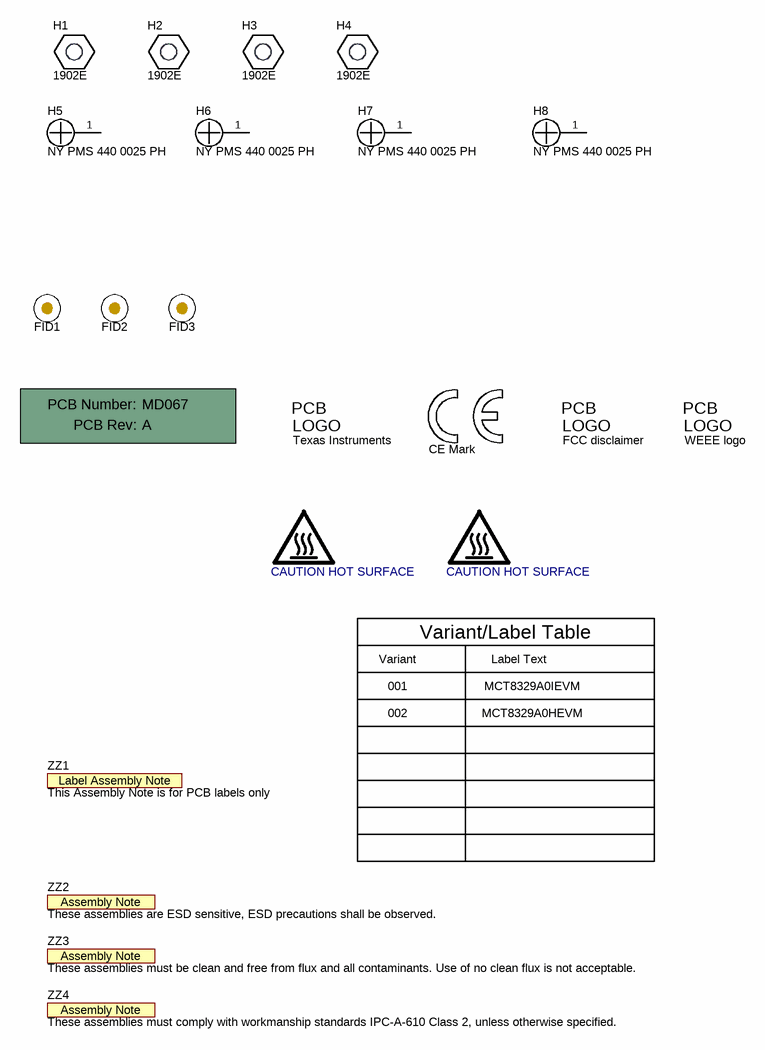
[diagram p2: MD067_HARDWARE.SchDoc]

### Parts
!PCB1  Printed Circuit Board  (value not drawn)  (mechanical)
FID1  Fiducial  [Fiducial10-20]  (value not drawn)
FID2  Fiducial  [Fiducial10-20]  (value not drawn)
FID3  Fiducial  [Fiducial10-20]  (value not drawn)
H1  1902E  [Keystone_1902E]
H2  1902E  [Keystone_1902E]
H3  1902E  [Keystone_1902E]
H4  1902E  [Keystone_1902E]
H5  NY PMS 440 0025 PH  [NY PMS 440 0025 PH]
H6  NY PMS 440 0025 PH  [NY PMS 440 0025 PH]
H7  NY PMS 440 0025 PH  [NY PMS 440 0025 PH]
H8  NY PMS 440 0025 PH  [NY PMS 440 0025 PH]
Logo1  CE Mark  [CE_Mark_5mm]  (no BOM)
Logo2  Texas Instruments  [TI_Stacked_Overlay_Small]  (no BOM)
Logo3  FCC disclaimer  [FCC_disclaimer]  (no BOM)
Logo4  WEEE logo  [WEEE_Minimum]  (no BOM)
LOGO5  CAUTION HOT SURFACE  [IEC_HotSurface_Small]  (no BOM)
LOGO6  CAUTION HOT SURFACE  [IEC_HotSurface_Small]  (no BOM)
ZZ1  This Assembly Note is for PCB labels only  [AssemblyNoteLabel]  (no BOM)
ZZ2  These assemblies are ESD sensitive, ESD precautions shall be observed.  [AssemblyNote]  (no BOM)
ZZ3  These assemblies must be clean and free from flux and all contaminants. Use of no clean flux is not acceptable.  [AssemblyNote]  (no BOM)
ZZ4  These assemblies must comply with workmanship standards IPC-A-610 Class 2, unless otherwise specified.  [AssemblyNote]  (no BOM)

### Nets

Not connected (* = marked no-connect by the designer): H5 1; H6 1; H7 1; H8 1

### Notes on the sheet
- Variant
- Variant/Label Table
- Label Text
- 001
- 002
- MCT8329A0IEVM
- MCT8329A0HEVM

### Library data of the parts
!PCB1 = CMP-0003618-2: Manufacturer: Any; PartNumber: MD067
FID1-FID3 = CMP-0077181-1: Fiducial mark.  There is nothing to buy or mount.
H1-H4 = 1902E: Standoff, Hex, 1"L #4-40 Nylon; Manufacturer: Keystone; SymbolCreator: a0412235; Green_Lifecycle: Active; Green_REACh: Passed
H5-H8 = NY PMS 440 0025 PH: Machine Screw, Round, #4-40 x 1/4, Nylon, Philips panhead; Manufacturer: B&F Fastener Supply; CompType: Hardware; SymbolCreator: codlsc; U/M: EA; Green_Lifecycle: Not Set; Green_REACh: Incomplete
Logo1 = CMP-0074844-1: SymbolCreator: a0412235
Logo2 = CMP-0074838-1: Texas Instrument Corporate Signature; SymbolCreator: a0412235; Lib Reference: TI_Logo; Library Reference: Logo
Logo3 = CMP-0074847-1: FCC_disclaimer; Library Reference: Logo
Logo4 = CMP-0074769-1
LOGO5 LOGO6 = CMP-0074837-1: IEC 61010-1 Hot Surface Warning; SymbolCreator: a0412235
ZZ1 = CMP-0003616-3
ZZ2 = CMP-0077236-1
ZZ3 = CMP-0077237-1
ZZ4 = CMP-0077238-1

## Sheet MD067_POWER_AND_CONNECTORS.SchDoc
size 431 x 279 mm; Date: Not shown in title block; ApprovedBy: Not shown in title block; CheckedBy: Not shown in title block; Author: Not shown in title block; CompanyName: Not shown in title block; Engineer: Not shown in title block; Organization: Not shown in title block; Address1: Not shown in title block; Address2: Not shown in title block; Address3: Not shown in title block; Address4: Not shown in title block; DocumentNumber: 4; Revision: Use project parameter SCH_Rev; SheetNumber: 4; SheetTotal: 5; PageSetup: Record=PageOptions¦CenterHorizontal=True¦CenterVertical=True¦PrintScale=1.00¦XCorrection=1.00¦YCorrection=1.00¦PrintKind=0¦BorderSize=5000000¦LeftOffset=0¦BottomOffset=0¦Orientation=2¦PaperLength=1000¦PaperWidth=1000¦Scale=100¦PaperSource=15¦PrintQuality=600¦MediaType=1¦DitherType=10¦PaperKind=Letter¦PrintScaleMode=1
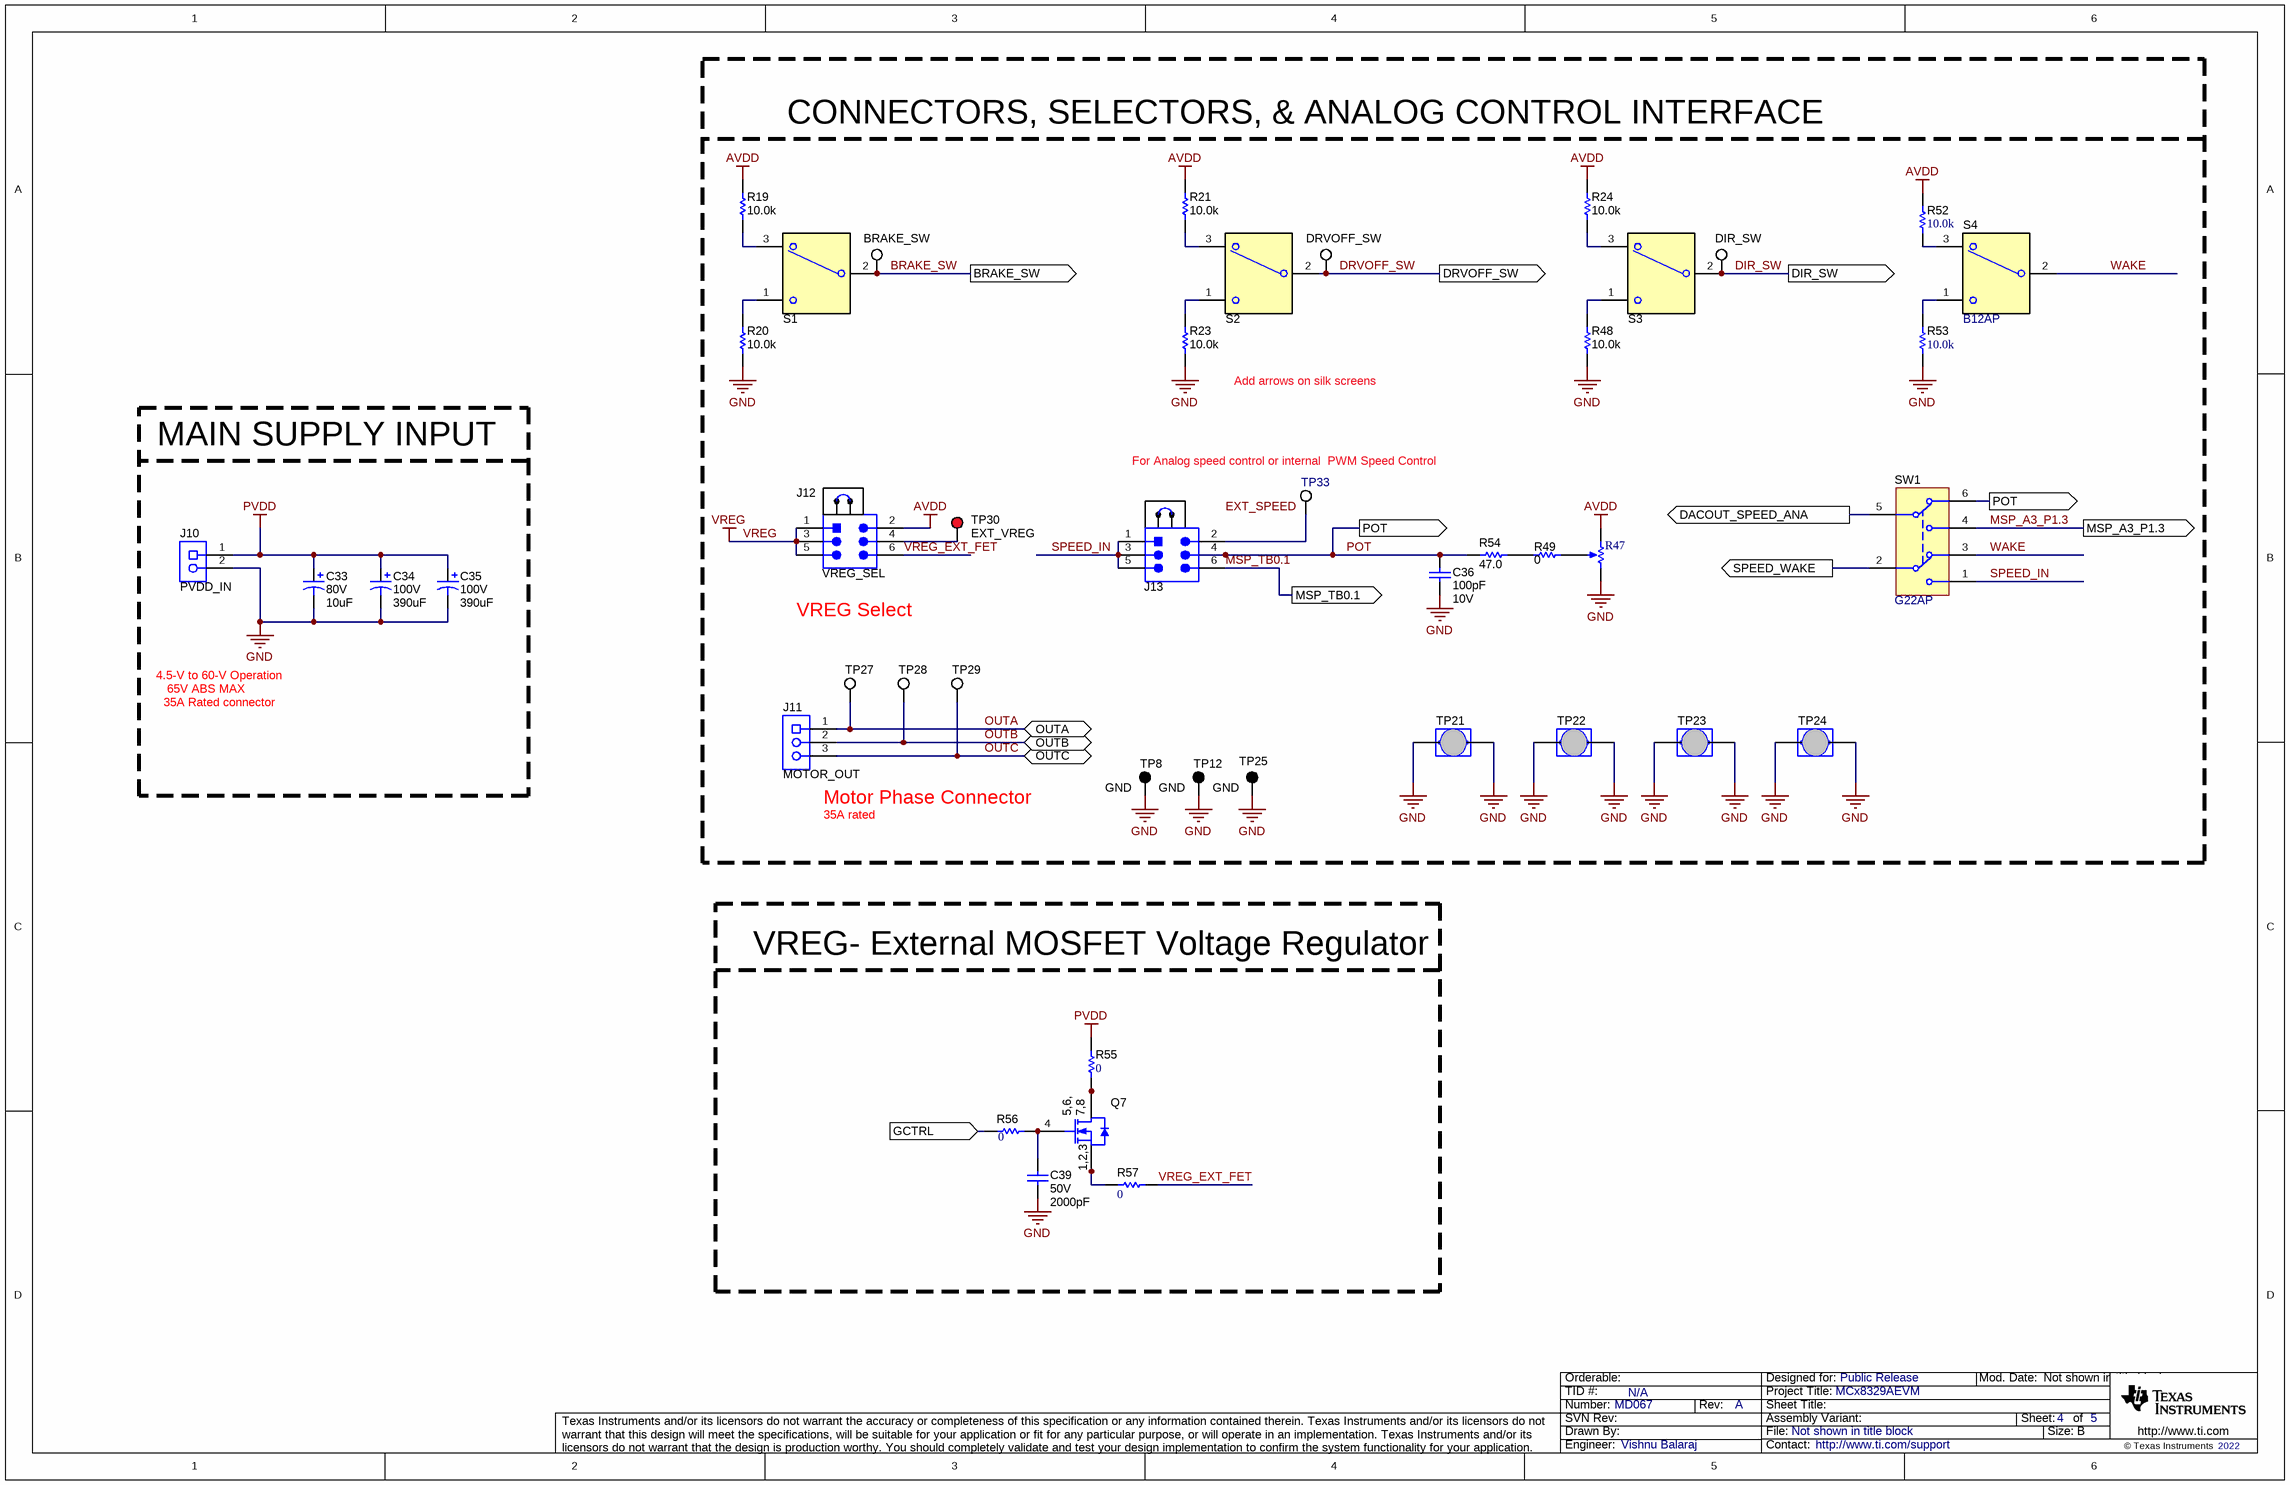
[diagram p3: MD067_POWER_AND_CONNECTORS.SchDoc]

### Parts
C33  VDC_V: 80V  ValueDisplayed: 10uF  [CAPSMT_62_F80]  (hidden comment: EMZA800ADA100MF80G)
C34  VDC_V: 100V  ValueDisplayed: 390uF  [KYB_1250x3500]  (hidden comment: EKYB101ELL391MK35S)
C35  VDC_V: 100V  ValueDisplayed: 390uF  [KYB_1250x3500]  (hidden comment: EKYB101ELL391MK35S)
C36  Cap_F: 100pF  VDC_V: 10V  [0603]  (hidden comment: 0603ZC101KAT2A)
C39  VDC_V: 50V  ValueDisplayed: 2000pF  [1206]  (hidden comment: 12065A202JAT2A)
J10  PVDD_IN  [Phoenix_1902547]
J11  MOTOR_OUT  [Phoenix_1904150]
J12  VREG_SEL  [TSW-103-07-G-D]
J13  Header_3x2  [TSW-103-07-G-D]  (value not drawn)
Q7  CSD18534Q5A  [DQJ0008A]  (value not drawn)
R19  ValueDisplayed: 10.0k  [0603L]  (hidden comment: ERA-3ARW103V)
R20  ValueDisplayed: 10.0k  [0603L]  (hidden comment: ERA-3ARW103V)
R21  ValueDisplayed: 10.0k  [0603L]  (hidden comment: ERA-3ARW103V)
R23  ValueDisplayed: 10.0k  [0603L]  (hidden comment: ERA-3ARW103V)
R24  ValueDisplayed: 10.0k  [0603L]  (hidden comment: ERA-3ARW103V)
R47  3352T-1-253LF  [Bourns_3352T]  (value not drawn)
R48  ValueDisplayed: 10.0k  [0603L]  (hidden comment: ERA-3ARW103V)
R49  ValueDisplayed: 0  [0603L]  (hidden comment: ERJ-3GEY0R00V)
R52  ValueDisplayed: 10.0k  [0603]  (hidden comment: ERA-3ARW103V)
R53  ValueDisplayed: 10.0k  [0603]  (hidden comment: ERA-3ARW103V)
R54  ValueDisplayed: 47.0  [0603]  (hidden comment: RT0603BRD0747RL)
R55  ValueDisplayed: 0  [0603]  (hidden comment: ERJ-3GEY0R00V)
R56  ValueDisplayed: 0  [0603]  (hidden comment: ERJ-3GEY0R00V)
R57  ValueDisplayed: 0  [0603]  (hidden comment: ERJ-3GEY0R00V)
S1  SW_SPDT_COM2_1_3  [SW_B12AP]  (value not drawn)
S2  SW_SPDT_COM2_1_3  [SW_B12AP]  (value not drawn)
S3  SW_SPDT_COM2_1_3  [SW_B12AP]  (value not drawn)
S4  B12AP  [SW_B12AP]
SH-J7  SNT-100-BK-G  [SNT-100-BK-G]  (value not drawn)
SH-J8  SNT-100-BK-G  [SNT-100-BK-G]  (value not drawn)
SW1  G22AP  [SW_G2xAP]
TP8  GND  [Keystone5001]
TP12  GND  [Keystone5001]
TP21  GND  [Harwin_D3082-05]  (value not drawn)
TP22  GND  [Harwin_D3082-05]  (value not drawn)
TP23  GND  [Harwin_D3082-05]  (value not drawn)
TP24  GND  [Harwin_D3082-05]  (value not drawn)
TP25  GND  [Keystone5001]
TP26  BRAKE_SW  [Keystone5002]
TP27  OUTA  [Testpoint_Keystone_Compact]  (value not drawn)
TP28  OUTB  [Testpoint_Keystone_Compact]  (value not drawn)
TP29  OUTC  [Testpoint_Keystone_Compact]  (value not drawn)
TP30  EXT_VREG  [Keystone5000]
TP31  DRVOFF_SW  [Keystone5002]
TP32  DIR_SW  [Keystone5002]
TP33  EXT_SPEED  [Keystone5002]  (value not drawn)

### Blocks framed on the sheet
CONNECTORS, SELECTORS, & ANALOG CONTROL INTERFACE: C36 J11-J13 R19-R21 R23 R24 R47-R49 R52-R54 S1-S4 SH-J7 SH-J8 SW1 TP8 TP12 TP21-TP33
MAIN SUPPLY INPUT: C33-C35 J10
VREG- External MOSFET Voltage Regulator: C39 Q7 R55-R57

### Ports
BRAKE_SW (out), DACOUT_SPEED_ANA (out), DIR_SW (out), DRVOFF_SW (out), GCTRL (in), MSP_A3_P1.3 (out), MSP_TB0.1 (out), OUTA (bidir), OUTB (bidir), OUTC (bidir), POT (out), SPEED_WAKE (out)

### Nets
AVDD: J12.2 R19.2 R21.2 R24.2 R47.1(CCW) R52.2
GND: C33.2(-) C34.2(-) C35.2(-) C36.2 C39.2 J10.2 R20.1 R23.1 R47.3(CW) R48.1 R53.1 TP8.1 TP12.1 TP21.1 TP21.2 TP22.1 TP22.2 TP23.1 TP23.2 TP24.1 TP24.2 TP25.1
PVDD: C33.1(+) C34.1(+) C35.1(+) J10.1 R55.2
VREG: J12.1 J12.3 J12.5
BRAKE_SW: S1.2(COM) TP26.1 ; port BRAKE_SW
DACOUT_SPEED_ANA: SW1.5 ; port DACOUT_SPEED_ANA
DIR_SW: S3.2(COM) TP32.1 ; port DIR_SW
DRVOFF_SW: S2.2(COM) TP31.1 ; port DRVOFF_SW
GCTRL: R56.1 ; port GCTRL
MSP_A3_P1.3: SW1.4 ; port MSP_A3_P1.3
MSP_TB0.1: J13.6 ; port MSP_TB0.1
OUTA: J11.1 TP27.1 ; port OUTA
OUTB: J11.2 TP28.1 ; port OUTB
OUTC: J11.3 TP29.1 ; port OUTC
POT: C36.1 J13.4 R54.1 SW1.6 ; port POT
SPEED_IN: J13.1 J13.3 J13.5 SW1.1
SPEED_WAKE: SW1.2 ; port SPEED_WAKE
VREG_EXT_FET: J12.6 R57.2
WAKE: S4.2(COM) SW1.3
NetC39_1: C39.1 Q7.4(G) R56.2
NetJ12_4: J12.4 TP30.1
NetJ13_2: J13.2 TP33.1
NetQ7_1: Q7.1(S) Q7.2(S) Q7.3(S) R57.1
NetQ7_5: Q7.5(D) Q7.6(D) Q7.7(D) Q7.8(D) Q7.9(D) R55.1
NetR19_1: R19.1 S1.3
NetR20_2: R20.2 S1.1
NetR21_1: R21.1 S2.3
NetR23_2: R23.2 S2.1
NetR24_1: R24.1 S3.3
NetR47_2: R47.2(WIPER) R49.2
NetR48_2: R48.2 S3.1
NetR49_1: R49.1 R54.2
NetR52_1: R52.1 S4.3
NetR53_2: R53.2 S4.1

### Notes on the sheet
- Add arrows on silk screens
- For Analog speed control or internal  PWM Speed Control
- VREG Select
- 65V ABS MAX
- 4.5-V to 60-V Operation
- 35A Rated connector
- (near J11) Motor Phase Connector
- 35A rated
- Labels drawn without touching a wire or pin: EXT_SPEED

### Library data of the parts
C33 = CMP-0011397-2: CAP, AL, 10 uF, 80 V, +/- 20%, 2.4 ohm, SMD; Manufacturer: Chemi-Con; TaMin_C: -55°C; ESR_ohm: 2.4; Polarized: Y; SizeAreaWB_mm2: 73.96; Value1: 2.4 ohm; U/M: EA; Value: 10uF; TaMax_C: 105°C; SizeZ_mm: 7.7; SizeX_mm: 6.6; Cap_Case: F80; SizeArea_mm2: 43.56; CompType: Capacitor; Cap_F: 10µF; IRMS_A: 60mA; AEC Category: Q200
C34 C35 = CMP-0009875-2: CAP, AL, 390 uF, 100 V, +/- 20%, 0.026 ohm, TH; Manufacturer: Chemi-Con; TaMin_C: -40°C; ESR_ohm: 0.026; Polarized: Y; SizeAreaWB_mm2: 210.25; U/M: EA; Value: 390uF; TaMax_C: 105°C; SizeZ_mm: 36.5; SizeX_mm: 12.5; Cap_Case: 12.5x35mm; SizeArea_mm2: 156.25; CompType: Capacitor; AEC Qualified: N; Cap_F: 390µF; IRMS_A: 2.25A; AEC Category: Q200
C36 = CMP-0006812-1: CAP, CERM, 100 pF, 10 V, +/- 10%, X7R, 0603; Manufacturer: AVX; TaMin_C: -55°C; Polarized: N; SizeAreaWB_mm2: 4.68; Value1: Unknown; U/M: EA; Value: 100pF; TaMax_C: 125°C; SizeZ_mm: 1; SizeX_mm: 1.6; SizeY_mm: 0.8; SizeArea_mm2: 1.28; AEC Category: Q200
C39 = CMP-0082630-1: CAP, CERM, 2000 pF, 50 V,+/- 5%, C0G/NP0, 1206; Manufacturer: AVX; Cap_F: 2nF; SizeAreaWB_mm2: 10.92; SizeArea_mm2: 5.12; AEC Qualified: N; AEC Category: Q200; Value: 2000pF; TaMax_C: 125°C; SizeZ_mm: 1.35; Green_REACh: Incomplete; TaMin_C: -55°C; SizeY_mm: 1.6; Green_Lifecycle: Active; U/M: EA; SizeX_mm: 3.2
J10 = CMP-0055527-1: Terminal Block, 9.52mm, 2x1, R/A, TH; Manufacturer: Phoenix Contact; PartNumber: 1902547; Cert_VDE: Y; CNHeader: FALSE; Current_A: 32A; Gender: Female; Voltage_V: 1kV; Row_Count: 1; Pitch_mm: 9.52; CT: TRUE
J11 = CMP-0055528-1: Terminal Block, 9.52mm, 3x1, R/A, TH; Manufacturer: Phoenix Contact; PartNumber: 1904150; Cert_VDE: Y; CNHeader: FALSE; Current_A: 32A; Gender: Female; Voltage_V: 1kV; Row_Count: 1; Pitch_mm: 9.52; CT: TRUE
J12 = CMP-0075406-2: Header, 100mil, 3x2, Gold, TH; Manufacturer: Samtec; Pitch_mm: 2.54; Cert_VDE: N; Gender: Male; Cert_CSA: Y; Voltage_V: 550V; Green_REACh: Passed; Current_A: 6.3A; Green_Lifecycle: Active; Row_Count: 2
J13 = CMP-0075406-2: Header, 100mil, 3x2, Gold, TH; Manufacturer: Samtec; Pitch_mm: 2.54; Gender: Male; Shrouded: N; Row_Count: 2; Current_A: 6.3A; Voltage_V: 550V; Cert_CSA: Y; Green_Lifecycle: Active; Green_REACh: Passed
Q7 = CMP-0000817-1: MOSFET, N-CH, 60 V, 50 A, DQJ0008A (VSONP-8); Alternate Manufacturer: None; Manufacturer: Texas Instruments; SizeZ_mm: 1.1; ChType: N; Value2: 22 nC; Value1: 0.009; VdsMax_V: 60V; SizeX_mm: 6; SizeY_mm: 4.9; Vgs_V: 2.3V; Value: 60V; Rdson45_ohm: 9.8m; SizeArea_mm2: 29.4; AEC Category: Q101; IdsMax_A: 50A; SizeAreaWB_mm2: 55.2; U/M: EA; QgTyp_nC: 22
R19-R21 R23 R24 R48 R52 R53 = CMP-0086251-1: RES, 10.0 k, 0.05%, 0.1 W, AEC-Q200 Grade 0, 0603; Manufacturer: Panasonic; Res_ohm: 10k; Value: 10.0k; SizeY_mm: 0.8; SizeArea_mm2: 1.28; SizeAreaWB_mm2: 4.68; AEC Grade: 0; Power_W: 100mW; SizeX_mm: 1.6; Value2: 0.1W; Value_Code: 10k0; SizeZ_mm: 1; AEC Qualified: Y; AEC Category: Q200; TempCo: 10 ppm/C
R47 = CMP-0001776-2: Trimmer Potentiometer, 25kohm, 0.5W, TH; Manufacturer: Bourns
R49 R55-R57 = CMP-0025874-4: as R1 on sheet MD067_DRIVER
R54 = CMP-0024269-1: RES, 47.0, 0.1%, 0.1 W, 0603; Manufacturer: Yageo America; Power_W: 100mW; TempCo: 25 ppm/C; Value_Code: 47R0; U/M: EA; Value: 47.0; EIA_Code: E192; Res_ohm: 47; SizeX_mm: 1.6; SizeY_mm: 0.8; SizeZ_mm: 1; Value2: 0.1W; SizeArea_mm2: 1.28; VDC_V: 75V; AEC Category: Q200
S1-S3 = CMP-0002155-2: SWITCH TOGGLE SPDT 0.4VA 28V; PartNumber: B12AP; Manufacturer: NKK Switches; SwitchFunction: On-On; PositionCount: 2; CurrentRating_mA: 100A
S4 = CMP-0002155-2: SWITCH TOGGLE SPDT 0.4VA 28V; Manufacturer: NKK Switches; CurrentRating_mA: 100A; PositionCount: 2; SwitchFunction: On-On
SH-J7 SH-J8 = CMP-0003623-3: as SH-J1 on sheet MD067_DRIVER
SW1 = CMP-0002204-1: Switch, DPDT, On-On, 0.4 VA, 28 V, TH; Manufacturer: NKK Switches; CurrentRating_mA: 400A; PositionCount: 2; VDC_V: 28V
TP8 TP12 TP25 = CMP-0055138-1: Test Point, Miniature, Black, TH; Manufacturer: Keystone; CNHeader: FALSE; Green_Lifecycle: Active; Green_REACh: Passed; ContactFinish: Silver; CT: TRUE
TP21-TP24 = CMP-0075110-1: 1mm Uninsulated Shorting Plug, 10.16mm spacing, TH; Manufacturer: Harwin; PartNumber: D3082-05; CNHeader: False; Green_Lifecycle: Active; Green_REACh: Passed; CompType: Jumper Wire
TP26 TP31-TP33 = CMP-0055139-1: as TP2 on sheet MD067_DRIVER
TP27-TP29 = CMP-0055153-1: Test Point, Compact, SMT; Manufacturer: Keystone; CNHeader: FALSE; Green_Lifecycle: Active; Green_REACh: Passed; CT: TRUE
TP30 = CMP-0055137-1: as TP1 on sheet MD067_DRIVER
